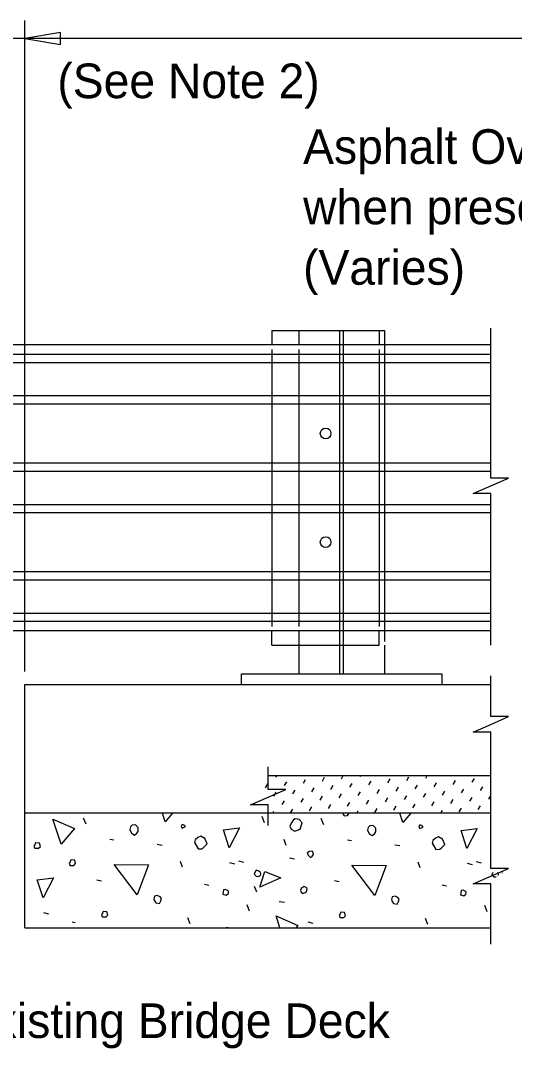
# Model space of a CAD drawing. Extents: x 21516.9 to 21589, y 56154.7 to 56194.3.
# Drawn here: x 21529.59 to 21532.46, y 56170 to 56175.99 of the extents above; entities that cross this region are included whole.
import ezdxf

# ---------------------------------------------------------------- set-up
doc = ezdxf.new("R2010")
doc.units = 0
for name, color, linetype in [('AdhocPoint_dp', 7, 'Continuous'), ('Border', 7, 'Continuous'), ('Patterning', 7, 'Continuous'), ('PlotBorder_dp', 7, 'Continuous'), ('SheetBorder_dp', 7, 'Continuous'), ('TextMisc', 7, 'Continuous')]:
    doc.layers.add(name, color=color, linetype=linetype)

msp = doc.modelspace()

# ---------------------------------------------------------------- linework, layer by layer
at = {"layer": 'AdhocPoint_dp'}
for p, q in [((21529.6122, 56170.707), (21529.6122, 56172.1237)), ((21529.6122, 56172.1237), (21532.3268, 56172.1237)), ((21531.0302, 56171.5926), (21532.3268, 56171.5926)), ((21532.3268, 56171.3737), (21529.6122, 56171.3737)), ((21529.6122, 56170.707), (21532.3268, 56170.707))]:
    msp.add_line(p, q, dxfattribs=at)
at = {"layer": 'Border'}
for p, q in [((21531.448, 56172.1862), (21531.448, 56174.1862)), ((21531.4689, 56172.1862), (21531.4689, 56174.1862)), ((21531.7084, 56174.1862), (21531.7084, 56172.3732)), ((21531.2084, 56174.0743), (21531.2084, 56172.4624))]:
    msp.add_line(p, q, dxfattribs=at)
at = {"layer": 'Patterning'}
for p, q in [((21531.0522, 56174.1862), (21531.6772, 56174.1862)), ((21531.0522, 56174.1862), (21531.0522, 56174.1029)), ((21531.6772, 56174.1862), (21531.6772, 56174.1029)), ((21531.0522, 56174.0743), (21531.0522, 56172.4624)), ((21531.6772, 56174.0743), (21531.6772, 56172.4624)), ((21531.0522, 56172.3529), (21531.0522, 56172.4362)), ((21531.6772, 56172.3529), (21531.6772, 56172.4362)), ((21531.0522, 56172.3529), (21531.6772, 56172.3529)), ((21531.076, 56171.584), (21531.0809, 56171.5926)), ((21531.1248, 56171.5351), (21531.1378, 56171.5575)), ((21531.2354, 56171.5481), (21531.2484, 56171.5705)), ((21531.3461, 56171.5611), (21531.359, 56171.5835)), ((21531.4567, 56171.574), (21531.4674, 56171.5926)), ((21531.5673, 56171.587), (21531.5706, 56171.5926)), ((21531.6162, 56171.5382), (21531.6291, 56171.5606)), ((21531.7268, 56171.5511), (21531.7398, 56171.5735)), ((21531.8374, 56171.5641), (21531.8504, 56171.5865)), ((21531.9481, 56171.5771), (21531.9571, 56171.5926)), ((21532.0587, 56171.59), (21532.0602, 56171.5926)), ((21532.1075, 56171.5412), (21532.1205, 56171.5636)), ((21532.2182, 56171.5541), (21532.2311, 56171.5765)), ((21531.0142, 56171.5222), (21531.0271, 56171.5446)), ((21531.1736, 56171.4863), (21531.1866, 56171.5087)), ((21531.2843, 56171.4993), (21531.2972, 56171.5217)), ((21531.3949, 56171.5122), (21531.4079, 56171.5346)), ((21531.5055, 56171.5252), (21531.5185, 56171.5476)), ((21531.5544, 56171.4764), (21531.5673, 56171.4988)), ((21531.665, 56171.4893), (21531.678, 56171.5117)), ((21531.7756, 56171.5023), (21531.7886, 56171.5247)), ((21531.8863, 56171.5153), (21531.8992, 56171.5376)), ((21531.9969, 56171.5282), (21532.0099, 56171.5506)), ((21532.0457, 56171.4794), (21532.0587, 56171.5018)), ((21532.1564, 56171.4923), (21532.1693, 56171.5147)), ((21532.267, 56171.5053), (21532.28, 56171.5277)), ((21531.063, 56171.4733), (21531.076, 56171.4957)), ((21531.1118, 56171.4245), (21531.1248, 56171.4469)), ((21531.2225, 56171.4375), (21531.2354, 56171.4599)), ((21531.3331, 56171.4504), (21531.3461, 56171.4728)), ((21531.4437, 56171.4634), (21531.4567, 56171.4858)), ((21531.6032, 56171.4275), (21531.6162, 56171.4499)), ((21531.7138, 56171.4405), (21531.7268, 56171.4629)), ((21531.8245, 56171.4535), (21531.8374, 56171.4758)), ((21531.9351, 56171.4664), (21531.9481, 56171.4888)), ((21531.9839, 56171.4176), (21531.9969, 56171.44)), ((21532.0946, 56171.4305), (21532.1075, 56171.4529)), ((21532.2052, 56171.4435), (21532.2182, 56171.4659)), ((21532.3158, 56171.4565), (21532.3268, 56171.4754)), ((21531.0564, 56171.3737), (21531.063, 56171.3851)), ((21531.1607, 56171.3757), (21531.1736, 56171.3981)), ((21531.2713, 56171.3886), (21531.2843, 56171.411)), ((21531.3819, 56171.4016), (21531.3949, 56171.424)), ((21531.4926, 56171.4146), (21531.5055, 56171.437)), ((21531.546, 56171.3737), (21531.5544, 56171.3881)), ((21531.652, 56171.3787), (21531.665, 56171.4011)), ((21531.7627, 56171.3917), (21531.7756, 56171.414)), ((21531.8733, 56171.4046), (21531.8863, 56171.427)), ((21531.9325, 56171.3737), (21531.9351, 56171.3782)), ((21532.0356, 56171.3737), (21532.0457, 56171.3911)), ((21532.1434, 56171.3817), (21532.1564, 56171.4041)), ((21532.254, 56171.3947), (21532.267, 56171.4171)), ((21529.9688, 56171.3105), (21529.9546, 56171.3459)), ((21531.0094, 56171.3187), (21530.9952, 56171.3541)), ((21531.3535, 56171.307), (21531.3393, 56171.3424)), ((21531.4429, 56171.3737), (21531.4437, 56171.3752)), ((21530.1067, 56171.2221), (21530.1314, 56171.2186)), ((21531.1349, 56171.1862), (21531.1225, 56171.2198)), ((21531.4913, 56171.2186), (21531.5161, 56171.2151)), ((21530.3824, 56171.1939), (21530.4125, 56171.1886)), ((21531.7671, 56171.1903), (21531.7972, 56171.185)), ((21530.5309, 56171.0595), (21530.5186, 56171.0931)), ((21530.8049, 56171.086), (21530.8332, 56171.079)), ((21530.8573, 56171.096), (21530.8856, 56171.0889)), ((21531.1537, 56171.1143), (21531.1838, 56171.109)), ((21531.9156, 56171.056), (21531.9032, 56171.0896)), ((21532.1896, 56171.0825), (21532.2179, 56171.0754)), ((21532.242, 56171.0925), (21532.2703, 56171.0854)), ((21530.0324, 56170.9853), (21530.0589, 56170.98)), ((21530.6582, 56170.9605), (21530.6847, 56170.9552)), ((21531.4171, 56170.9817), (21531.4436, 56170.9764)), ((21530.9634, 56170.9134), (21530.951, 56170.947)), ((21532.0429, 56170.957), (21532.0694, 56170.9517)), ((21530.921, 56170.8038), (21530.9068, 56170.8392)), ((21531.0936, 56170.8598), (21531.1254, 56170.8562)), ((21529.721, 56170.7953), (21529.7493, 56170.7882)), ((21532.3057, 56170.8003), (21532.2915, 56170.8356)), ((21529.8886, 56170.7419), (21529.9051, 56170.7378)), ((21530.5751, 56170.7289), (21530.561, 56170.7643)), ((21531.2615, 56170.7413), (21531.2898, 56170.7342)), ((21531.9598, 56170.7254), (21531.9457, 56170.7608))]:
    msp.add_line(p, q, dxfattribs=at)
for points in [[(21529.8239, 56171.1929), (21529.7761, 56171.3396), (21529.9016, 56171.2848), (21529.8239, 56171.1929)], [(21530.4302, 56171.3229), (21530.4136, 56171.3737)], [(21530.4731, 56171.3737), (21530.4302, 56171.3229)], [(21531.1632, 56171.2816), (21531.1861, 56171.2693), (21531.2162, 56171.2816), (21531.2286, 56171.3187), (21531.2109, 56171.3364), (21531.1879, 56171.3417), (21531.1773, 56171.3347), (21531.1649, 56171.3152), (21531.1561, 56171.2993), (21531.1632, 56171.2816)], [(21531.4633, 56171.3737), (21531.4719, 56171.3583), (21531.4913, 56171.36), (21531.5002, 56171.3724), (21531.5003, 56171.3737)], [(21531.8148, 56171.3194), (21531.7972, 56171.3737)], [(21531.8608, 56171.3737), (21531.8148, 56171.3194)], [(21530.2233, 56171.2787), (21530.2339, 56171.2575), (21530.2516, 56171.2469), (21530.2658, 56171.2575), (21530.2728, 56171.2681), (21530.2728, 56171.2893), (21530.2569, 56171.3052), (21530.2375, 56171.3035), (21530.2286, 56171.2946), (21530.2233, 56171.2787)], [(21530.5292, 56171.2876), (21530.5486, 56171.2964), (21530.5415, 56171.3035), (21530.5292, 56171.3088), (21530.5239, 56171.2964), (21530.5292, 56171.2876)], [(21530.8025, 56171.172), (21530.769, 56171.2763), (21530.8626, 56171.2887), (21530.8025, 56171.172)], [(21531.608, 56171.2752), (21531.6186, 56171.254), (21531.6363, 56171.2434), (21531.6504, 56171.254), (21531.6575, 56171.2646), (21531.6575, 56171.2858), (21531.6416, 56171.3017), (21531.6222, 56171.2999), (21531.6133, 56171.2911), (21531.608, 56171.2752)], [(21531.9138, 56171.284), (21531.9333, 56171.2929), (21531.9262, 56171.2999), (21531.9138, 56171.3052), (21531.9085, 56171.2929), (21531.9138, 56171.284)], [(21532.1872, 56171.1685), (21532.1536, 56171.2728), (21532.2473, 56171.2852), (21532.1872, 56171.1685)], [(21529.6709, 56171.1694), (21529.6921, 56171.1694), (21529.7027, 56171.18), (21529.6974, 56171.1995), (21529.6745, 56171.2012), (21529.6709, 56171.1906), (21529.6656, 56171.1818), (21529.6709, 56171.1694), (21529.6674, 56171.1729)], [(21530.5999, 56171.2027), (21530.6229, 56171.1656), (21530.6458, 56171.1673), (21530.6547, 56171.1762), (21530.6741, 56171.1956), (21530.6617, 56171.2257), (21530.637, 56171.2398), (21530.6193, 56171.2328), (21530.6052, 56171.2186), (21530.5999, 56171.2027)], [(21531.9845, 56171.1992), (21532.0075, 56171.162), (21532.0305, 56171.1638), (21532.0393, 56171.1726), (21532.0588, 56171.1921), (21532.0464, 56171.2221), (21532.0217, 56171.2363), (21532.004, 56171.2292), (21531.9899, 56171.2151), (21531.9845, 56171.1992)], [(21531.2651, 56171.1267), (21531.2757, 56171.1161), (21531.2863, 56171.1232), (21531.2934, 56171.1338), (21531.2898, 56171.1514), (21531.281, 56171.1532), (21531.2686, 56171.1514), (21531.258, 56171.1408), (21531.2651, 56171.1267)], [(21529.8763, 56171.0701), (21529.8975, 56171.0701), (21529.9081, 56171.0807), (21529.9028, 56171.1002), (21529.8798, 56171.1019), (21529.8763, 56171.0913), (21529.871, 56171.0825), (21529.8763, 56171.0701), (21529.8727, 56171.0737)], [(21530.2675, 56170.8986), (21530.1332, 56171.0754), (21530.3329, 56171.0737), (21530.2675, 56170.8986)], [(21530.9599, 56171.0076), (21530.9722, 56171.0059), (21530.9846, 56171.0112), (21530.9882, 56171.0218), (21530.9829, 56171.0306), (21530.9722, 56171.0377), (21530.9599, 56171.043), (21530.9528, 56171.0288), (21530.9493, 56171.0182), (21530.9599, 56171.0076)], [(21530.9822, 56170.9428), (21531.0105, 56171.0348), (21531.1042, 56170.9976), (21530.9822, 56170.9428)], [(21531.6522, 56170.8951), (21531.5179, 56171.0719), (21531.7176, 56171.0701), (21531.6522, 56170.8951)], [(21532.3389, 56171.0281), (21532.3375, 56171.0253), (21532.3339, 56171.0147), (21532.3445, 56171.0041)], [(21532.3701, 56171.0101), (21532.3728, 56171.0182), (21532.3675, 56171.0271), (21532.3659, 56171.0281)], [(21532.393, 56171.0243), (21532.3942, 56171.0281)], [(21529.7187, 56170.8813), (21529.6851, 56170.9856), (21529.7788, 56170.9979)], [(21529.7788, 56170.9979), (21529.7187, 56170.8813)], [(21532.3445, 56171.0041), (21532.3569, 56171.0023), (21532.3588, 56171.0031)], [(21530.766, 56170.9022), (21530.7855, 56170.8969), (21530.7979, 56170.9057), (21530.7996, 56170.9181), (21530.7961, 56170.9216), (21530.782, 56170.9287), (21530.7696, 56170.9269), (21530.7678, 56170.9146), (21530.766, 56170.9022)], [(21531.2297, 56170.9075), (21531.2368, 56170.9075), (21531.2509, 56170.9146), (21531.2562, 56170.9305), (21531.2545, 56170.9393), (21531.2403, 56170.9464), (21531.2226, 56170.9358), (21531.2191, 56170.9252), (21531.2226, 56170.9146), (21531.2297, 56170.9075)], [(21532.1507, 56170.8986), (21532.1702, 56170.8933), (21532.1825, 56170.9022), (21532.1843, 56170.9146), (21532.1808, 56170.9181), (21532.1666, 56170.9252), (21532.1543, 56170.9234), (21532.1525, 56170.911), (21532.1507, 56170.8986)], [(21530.3665, 56170.8668), (21530.3754, 56170.8509), (21530.3966, 56170.8474), (21530.4054, 56170.8633), (21530.409, 56170.8774), (21530.4001, 56170.8863), (21530.3842, 56170.8951), (21530.3683, 56170.8898), (21530.363, 56170.8739), (21530.3665, 56170.8668)], [(21531.7512, 56170.8633), (21531.76, 56170.8474), (21531.7813, 56170.8438), (21531.7901, 56170.8598), (21531.7936, 56170.8739), (21531.7848, 56170.8827), (21531.7689, 56170.8916), (21531.753, 56170.8863), (21531.7477, 56170.8704), (21531.7512, 56170.8633)], [(21530.0642, 56170.7696), (21530.0855, 56170.7696), (21530.0961, 56170.7802), (21530.0908, 56170.7997), (21530.0678, 56170.8014), (21530.0642, 56170.7908), (21530.0589, 56170.782), (21530.0642, 56170.7696), (21530.0607, 56170.7731)], [(21531.4489, 56170.7661), (21531.4701, 56170.7661), (21531.4807, 56170.7767), (21531.4754, 56170.7961), (21531.4525, 56170.7979), (21531.4489, 56170.7873), (21531.4436, 56170.7784), (21531.4489, 56170.7661), (21531.4454, 56170.7696)], [(21531.0988, 56170.707), (21531.0765, 56170.7755), (21531.2021, 56170.7207), (21531.1905, 56170.707)], [(21530.7968, 56170.707), (21530.7902, 56170.7084), (21530.7862, 56170.707)]]:
    msp.add_lwpolyline(points, dxfattribs=at)
at = {"layer": 'PlotBorder_dp'}
for p, q in [((21529.6122, 56172.2), (21529.6122, 56175.9911)), ((21533.5339, 56175.8862), (21528.2397, 56175.8862))]:
    msp.add_line(p, q, dxfattribs=at)
msp.add_lwpolyline([(21529.6121, 56175.8862), (21529.8204, 56175.8509), (21529.8204, 56175.9215)], close=True, dxfattribs=at)
for points in [[(21532.3268, 56172.3532), (21532.3268, 56173.2364), (21532.2234, 56173.2364), (21532.3268, 56173.2814), (21532.4301, 56173.3264), (21532.3268, 56173.3264), (21532.3268, 56174.1994)], [(21532.3268, 56171.3763), (21532.3268, 56171.8464), (21532.2234, 56171.8464), (21532.3268, 56171.8914), (21532.4301, 56171.9364), (21532.3268, 56171.9364), (21532.3268, 56172.1738)], [(21531.0302, 56171.3017), (21531.0302, 56171.4226), (21530.9268, 56171.4226), (21531.0302, 56171.4676), (21531.1335, 56171.5126), (21531.0302, 56171.5126), (21531.0302, 56171.6432)], [(21532.3268, 56170.6112), (21532.3268, 56170.9619), (21532.2234, 56170.9619), (21532.3268, 56171.0069), (21532.4301, 56171.0519), (21532.3268, 56171.0519), (21532.3268, 56171.3763)]]:
    msp.add_lwpolyline(points, dxfattribs=at)
at = {"layer": 'TextMisc'}
for p, q in [((21531.2084, 56174.1862), (21531.7084, 56174.1862)), ((21531.2084, 56174.1862), (21531.2084, 56174.1029)), ((21532.3268, 56174.1029), (21524.1864, 56174.1029)), ((21524.1864, 56174.0473), (21532.3268, 56174.0473)), ((21524.1864, 56173.9991), (21532.3268, 56173.9991)), ((21524.1864, 56173.8063), (21532.3268, 56173.8063)), ((21524.1864, 56173.7581), (21532.3268, 56173.7581)), ((21524.1864, 56173.4141), (21532.3268, 56173.4141)), ((21524.1864, 56173.3659), (21532.3268, 56173.3659)), ((21524.1864, 56173.1731), (21532.3268, 56173.1731)), ((21524.1864, 56173.1249), (21532.3268, 56173.1249)), ((21524.1864, 56172.781), (21532.3268, 56172.781)), ((21524.1864, 56172.7328), (21532.3268, 56172.7328)), ((21524.1864, 56172.5399), (21532.3268, 56172.5399)), ((21524.1864, 56172.4917), (21532.3268, 56172.4917)), ((21532.3268, 56172.4362), (21524.1864, 56172.4362)), ((21531.2084, 56172.4362), (21531.2084, 56172.1862)), ((21531.7084, 56172.3529), (21531.7084, 56172.1862)), ((21530.8751, 56172.1862), (21532.0418, 56172.1862)), ((21530.8751, 56172.1237), (21530.8751, 56172.1862)), ((21531.2084, 56172.1862), (21531.7084, 56172.1862)), ((21532.0418, 56172.1862), (21532.0418, 56172.1237)), ((21530.8751, 56172.1237), (21532.0418, 56172.1237))]:
    msp.add_line(p, q, dxfattribs=at)
for centre in [(21531.3647, 56173.5861), (21531.3647, 56172.953)]:
    msp.add_circle(centre, 0.0312, dxfattribs=at)

# ---------------------------------------------------------------- texts
at = {"layer": 'PlotBorder_dp'}
for s, p in [('Asphalt Overlay', (21531.2336, 56175.1564)), ('when present', (21531.2336, 56174.8044)), ('(Varies)', (21531.2336, 56174.4524))]:
    msp.add_text(s, height=0.2016, dxfattribs=at).set_placement(p)
at = {"layer": 'SheetBorder_dp'}
for s, p in [('(See Note 2)', (21529.8018, 56175.539)), ('Existing Bridge Deck', (21529.2516, 56170.0644))]:
    msp.add_text(s, height=0.2016, dxfattribs=at).set_placement(p)

doc.saveas('drawing.dxf')
